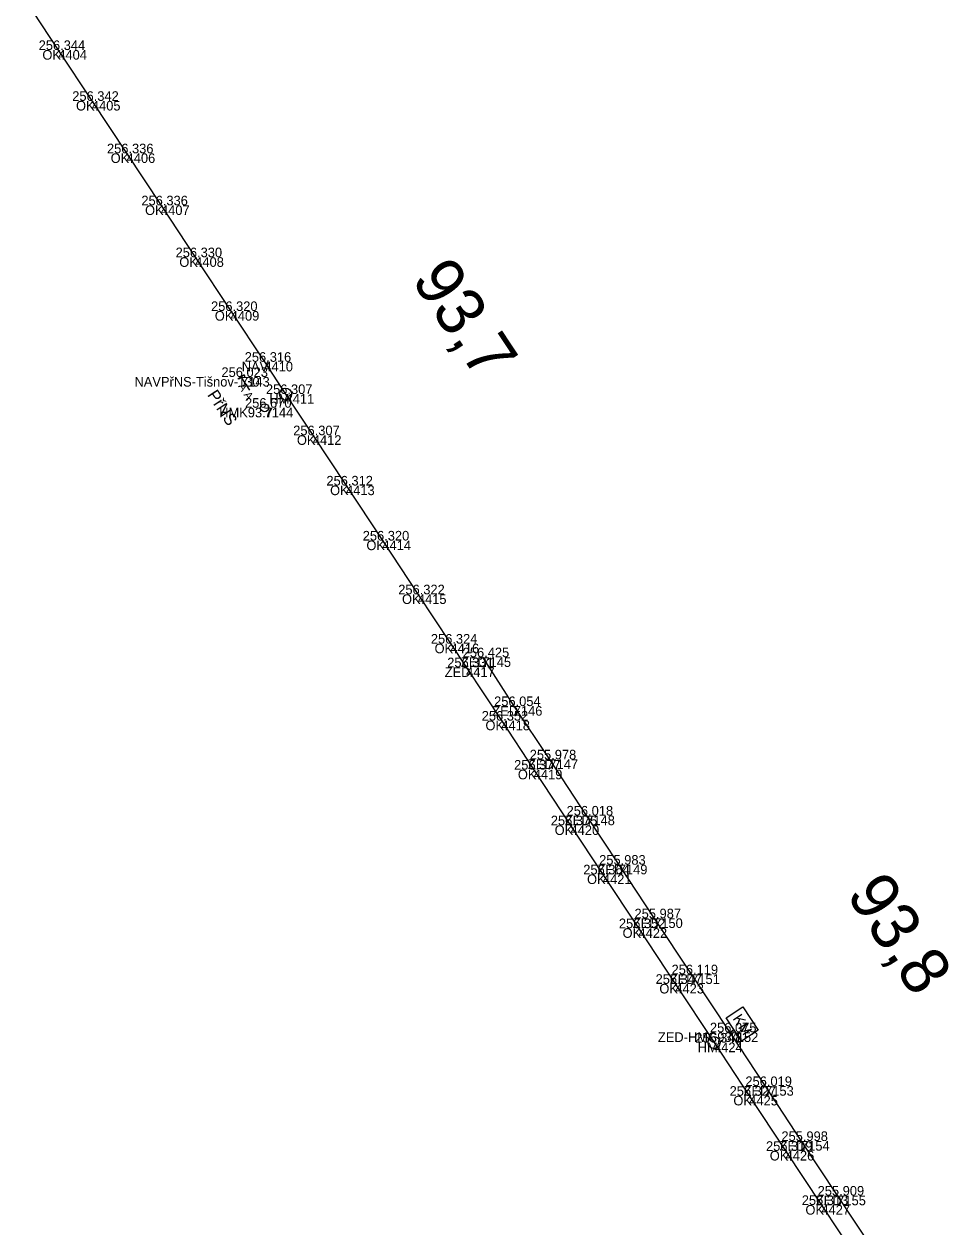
# Model space of a CAD drawing. Extents: x -621782 to -610392, y -1141853 to -1122321.
# Drawn here: x -610808.7 to -610693.4, y -1141393.8 to -1141243.8 of the extents above; entities that cross this region are included whole.
import ezdxf

# ---------------------------------------------------------------- set-up
doc = ezdxf.new("R2010")
doc.units = 0
for name, color, linetype in [('Vrstva 1', 7, 'Continuous'), ('Vrstva 13', 7, 'Continuous'), ('Vrstva 6', 7, 'Continuous'), ('Vrstva 60', 7, 'Continuous'), ('Vrstva 61', 7, 'Continuous'), ('Vrstva 62', 7, 'Continuous'), ('Vrstva 7', 7, 'Continuous')]:
    doc.layers.add(name, color=color, linetype=linetype)

msp = doc.modelspace()

# ---------------------------------------------------------------- linework, layer by layer
at = {"layer": 'Vrstva 1'}
msp.add_lwpolyline([(-610808.74, -1141240.54), (-610804.47, -1141247.02), (-610800.28, -1141253.36), (-610795.95, -1141259.9), (-610791.66, -1141266.39), (-610787.39, -1141272.86), (-610782.97, -1141279.57), (-610778.77, -1141285.9), (-610776.12, -1141289.92), (-610772.72, -1141295.06), (-610768.58, -1141301.33), (-610764.05, -1141308.19), (-610759.62, -1141314.9), (-610755.55, -1141321.05), (-610753.6, -1141324), (-610749.21, -1141330.65), (-610745.17, -1141336.77), (-610740.58, -1141343.71), (-610736.54, -1141349.83), (-610732.1, -1141356.54), (-610727.51, -1141363.48), (-610722.68, -1141370.8), (-610718.29, -1141377.44), (-610713.75, -1141384.31), (-610709.29, -1141391.06), (-610704.89, -1141397.72)], dxfattribs=at)
at = {"layer": 'Vrstva 13'}
msp.add_lwpolyline([(-610751.57, -1141322.75), (-610747.66, -1141328.84), (-610743.21, -1141335.49), (-610738.62, -1141342.49), (-610734.56, -1141348.62), (-610730.15, -1141355.31), (-610725.53, -1141362.29), (-610720.73, -1141369.53), (-610716.31, -1141376.23), (-610711.83, -1141383.08), (-610707.31, -1141389.89), (-610702.91, -1141396.53)], dxfattribs=at)
at = {"layer": 'Vrstva 6'}
for p, q in [((-610781.25, -1141287.51), (-610782.09, -1141288.07)), ((-610780.58, -1141289.44), (-610781.67, -1141287.79))]:
    msp.add_line(p, q, dxfattribs=at)
at = {"layer": 'Vrstva 60'}
for p, q in [((-610804.47, -1141247.02), (-610804.47, -1141247.02)), ((-610800.28, -1141253.36), (-610800.28, -1141253.36)), ((-610795.95, -1141259.9), (-610795.95, -1141259.9)), ((-610791.66, -1141266.39), (-610791.66, -1141266.39)), ((-610787.39, -1141272.86), (-610787.39, -1141272.86)), ((-610782.97, -1141279.57), (-610782.97, -1141279.57)), ((-610778.77, -1141285.9), (-610778.77, -1141285.9)), ((-610781.67, -1141287.79), (-610781.67, -1141287.79)), ((-610776.12, -1141289.92), (-610776.12, -1141289.92)), ((-610778.73, -1141291.63), (-610778.73, -1141291.63)), ((-610772.72, -1141295.06), (-610772.72, -1141295.06)), ((-610768.58, -1141301.33), (-610768.58, -1141301.33)), ((-610764.05, -1141308.19), (-610764.05, -1141308.19)), ((-610759.62, -1141314.9), (-610759.62, -1141314.9)), ((-610755.55, -1141321.05), (-610755.55, -1141321.05)), ((-610753.6, -1141324), (-610753.6, -1141324)), ((-610751.57, -1141322.75), (-610751.57, -1141322.75)), ((-610747.66, -1141328.84), (-610747.66, -1141328.84)), ((-610749.21, -1141330.65), (-610749.21, -1141330.65)), ((-610743.21, -1141335.49), (-610743.21, -1141335.49)), ((-610745.17, -1141336.77), (-610745.17, -1141336.77)), ((-610738.62, -1141342.49), (-610738.62, -1141342.49)), ((-610740.58, -1141343.71), (-610740.58, -1141343.71)), ((-610734.56, -1141348.62), (-610734.56, -1141348.62)), ((-610736.54, -1141349.83), (-610736.54, -1141349.83)), ((-610730.15, -1141355.31), (-610730.15, -1141355.31)), ((-610732.1, -1141356.54), (-610732.1, -1141356.54)), ((-610725.53, -1141362.29), (-610725.53, -1141362.29)), ((-610727.51, -1141363.48), (-610727.51, -1141363.48)), ((-610720.73, -1141369.53), (-610720.73, -1141369.53)), ((-610722.68, -1141370.8), (-610722.68, -1141370.8)), ((-610716.31, -1141376.23), (-610716.31, -1141376.23)), ((-610718.29, -1141377.44), (-610718.29, -1141377.44)), ((-610711.83, -1141383.08), (-610711.83, -1141383.08)), ((-610713.75, -1141384.31), (-610713.75, -1141384.31)), ((-610707.31, -1141389.89), (-610707.31, -1141389.89)), ((-610709.29, -1141391.06), (-610709.29, -1141391.06))]:
    msp.add_line(p, q, dxfattribs=at)
at = {"layer": 'Vrstva 7'}
for p, q in [((-610778.76, -1141291.59), (-610778.7, -1141291.67)), ((-610719.22, -1141367.31), (-610720.26, -1141367.99)), ((-610718.76, -1141368), (-610719.91, -1141367.77)), ((-610719.49, -1141367.85), (-610719.8, -1141368.69)), ((-610720.73, -1141369.53), (-610720.21, -1141369.18))]:
    msp.add_line(p, q, dxfattribs=at)
msp.add_lwpolyline([(-610721.17, -1141367.73), (-610719.1, -1141366.36), (-610717.18, -1141369.27), (-610719.25, -1141370.64)], close=True, dxfattribs=at)
msp.add_lwpolyline([(-610719.57, -1141369.03), (-610718.53, -1141368.35), (-610719.3, -1141369.44), (-610718, -1141369.14), (-610719.04, -1141369.83)], dxfattribs=at)
for centre, radius in [((-610776.12, -1141289.92), 0.75), ((-610778.73, -1141291.63), 0.5), ((-610722.68, -1141370.8), 0.75)]:
    msp.add_circle(centre, radius, dxfattribs=at)

# ---------------------------------------------------------------- texts
at = {"layer": 'Vrstva 6'}
for s, height, p in [('PřNS', 1.5, (-610785.94, -1141290.02)), ('  A A ', 1, (-610782.5, -1141288.34))]:
    msp.add_text(s, height=height, rotation=303.4129, dxfattribs=at).set_placement(p)
at = {"layer": 'Vrstva 60'}
for s, p in [('4404', (-610804.47, -1141248.22)), ('4405', (-610800.28, -1141254.56)), ('4406', (-610795.95, -1141261.1)), ('4407', (-610791.66, -1141267.59)), ('4408', (-610787.39, -1141274.06)), ('4409', (-610782.97, -1141280.77)), ('4410', (-610778.77, -1141287.1)), ('7143', (-610781.67, -1141288.99)), ('4411', (-610776.12, -1141291.12)), ('7144', (-610778.73, -1141292.83)), ('4412', (-610772.72, -1141296.26)), ('4413', (-610768.58, -1141302.53)), ('4414', (-610764.05, -1141309.39)), ('4415', (-610759.62, -1141316.1)), ('4416', (-610755.55, -1141322.25)), ('4417', (-610753.6, -1141325.2)), ('7145', (-610751.57, -1141323.95)), ('7146', (-610747.66, -1141330.04)), ('4418', (-610749.21, -1141331.85)), ('7147', (-610743.21, -1141336.69)), ('4419', (-610745.17, -1141337.97)), ('7148', (-610738.62, -1141343.69)), ('4420', (-610740.58, -1141344.91)), ('7149', (-610734.56, -1141349.82)), ('4421', (-610736.54, -1141351.03)), ('7150', (-610730.15, -1141356.51)), ('4422', (-610732.1, -1141357.74)), ('7151', (-610725.53, -1141363.49)), ('4423', (-610727.51, -1141364.68)), ('7152', (-610720.73, -1141370.73)), ('4424', (-610722.68, -1141372)), ('7153', (-610716.31, -1141377.43)), ('4425', (-610718.29, -1141378.64)), ('7154', (-610711.83, -1141384.28)), ('4426', (-610713.75, -1141385.51)), ('7155', (-610707.31, -1141391.09)), ('4427', (-610709.29, -1141392.26))]:
    msp.add_text(s, height=1.2, dxfattribs=at).set_placement(p)
at = {"layer": 'Vrstva 61'}
for s, p in [('256.344', (-610806.92, -1141247.02)), ('256.342', (-610802.73, -1141253.36)), ('256.336', (-610798.4, -1141259.9)), ('256.336', (-610794.11, -1141266.39)), ('256.330', (-610789.84, -1141272.86)), ('256.320', (-610785.42, -1141279.57)), ('256.316', (-610781.22, -1141285.9)), ('256.023', (-610784.12, -1141287.79)), ('256.307', (-610778.57, -1141289.92)), ('256.670', (-610781.18, -1141291.63)), ('256.307', (-610775.17, -1141295.06)), ('256.312', (-610771.03, -1141301.33)), ('256.320', (-610766.5, -1141308.19)), ('256.322', (-610762.07, -1141314.9)), ('256.324', (-610758, -1141321.05)), ('256.425', (-610754.03, -1141322.75)), ('256.331', (-610755.96, -1141324)), ('256.054', (-610750.11, -1141328.84)), ('256.352', (-610751.66, -1141330.65)), ('255.978', (-610745.67, -1141335.49)), ('256.377', (-610747.62, -1141336.77)), ('256.018', (-610741.07, -1141342.49)), ('256.375', (-610743.04, -1141343.71)), ('255.983', (-610737.01, -1141348.62)), ('256.364', (-610738.99, -1141349.83)), ('255.987', (-610732.6, -1141355.31)), ('256.352', (-610734.55, -1141356.54)), ('256.119', (-610727.98, -1141362.29)), ('256.347', (-610729.97, -1141363.48)), ('256.075', (-610723.19, -1141369.53)), ('256.341', (-610725.03, -1141370.8)), ('256.019', (-610718.77, -1141376.23)), ('256.327', (-610720.74, -1141377.44)), ('255.998', (-610714.28, -1141383.08)), ('256.319', (-610716.2, -1141384.31)), ('256.313', (-610711.74, -1141391.06)), ('255.909', (-610709.76, -1141389.89))]:
    msp.add_text(s, height=1.2, dxfattribs=at).set_placement(p)
at = {"layer": 'Vrstva 62'}
for s, p in [('OK', (-610806.45, -1141248.22)), ('OK', (-610802.26, -1141254.56)), ('OK', (-610797.94, -1141261.1)), ('OK', (-610793.65, -1141267.59)), ('OK', (-610789.38, -1141274.06)), ('OK', (-610784.95, -1141280.77)), ('NAV', (-610781.59, -1141287.1)), ('NAVPřNS-Tišnov-130', (-610794.97, -1141288.99)), ('HM', (-610778.15, -1141291.12)), ('HMK93.7', (-610784.4, -1141292.83)), ('OK', (-610774.71, -1141296.26)), ('OK', (-610770.57, -1141302.53)), ('OK', (-610766.04, -1141309.39)), ('OK', (-610761.6, -1141316.1)), ('OK', (-610757.54, -1141322.25)), ('ZED', (-610756.27, -1141325.2)), ('ZED', (-610754.25, -1141323.95)), ('ZED', (-610750.33, -1141330.04)), ('OK', (-610751.19, -1141331.85)), ('ZED', (-610745.89, -1141336.69)), ('OK', (-610747.15, -1141337.97)), ('ZED', (-610741.29, -1141343.69)), ('OK', (-610742.56, -1141344.91)), ('ZED', (-610737.23, -1141349.82)), ('OK', (-610738.52, -1141351.03)), ('ZED', (-610732.82, -1141356.51)), ('OK', (-610734.09, -1141357.74)), ('ZED', (-610728.2, -1141363.49)), ('OK', (-610729.5, -1141364.68)), ('ZED-HMC93.8', (-610729.68, -1141370.73)), ('HM', (-610724.71, -1141372)), ('ZED', (-610718.99, -1141377.43)), ('OK', (-610720.27, -1141378.64)), ('ZED', (-610714.5, -1141384.28)), ('OK', (-610715.73, -1141385.51)), ('ZED', (-610709.98, -1141391.09)), ('OK', (-610711.28, -1141392.26))]:
    msp.add_text(s, height=1.2, dxfattribs=at).set_placement(p)
at = {"layer": 'Vrstva 7'}
for s, rotation, p in [('93,7', 303.4862, (-610760.51, -1141275.65)), ('93,8', 303.4645, (-610706.28, -1141352.32))]:
    msp.add_text(s, height=6, rotation=rotation, dxfattribs=at).set_placement(p)

doc.saveas('drawing.dxf')
